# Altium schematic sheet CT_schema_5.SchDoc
size 373 x 245 mm
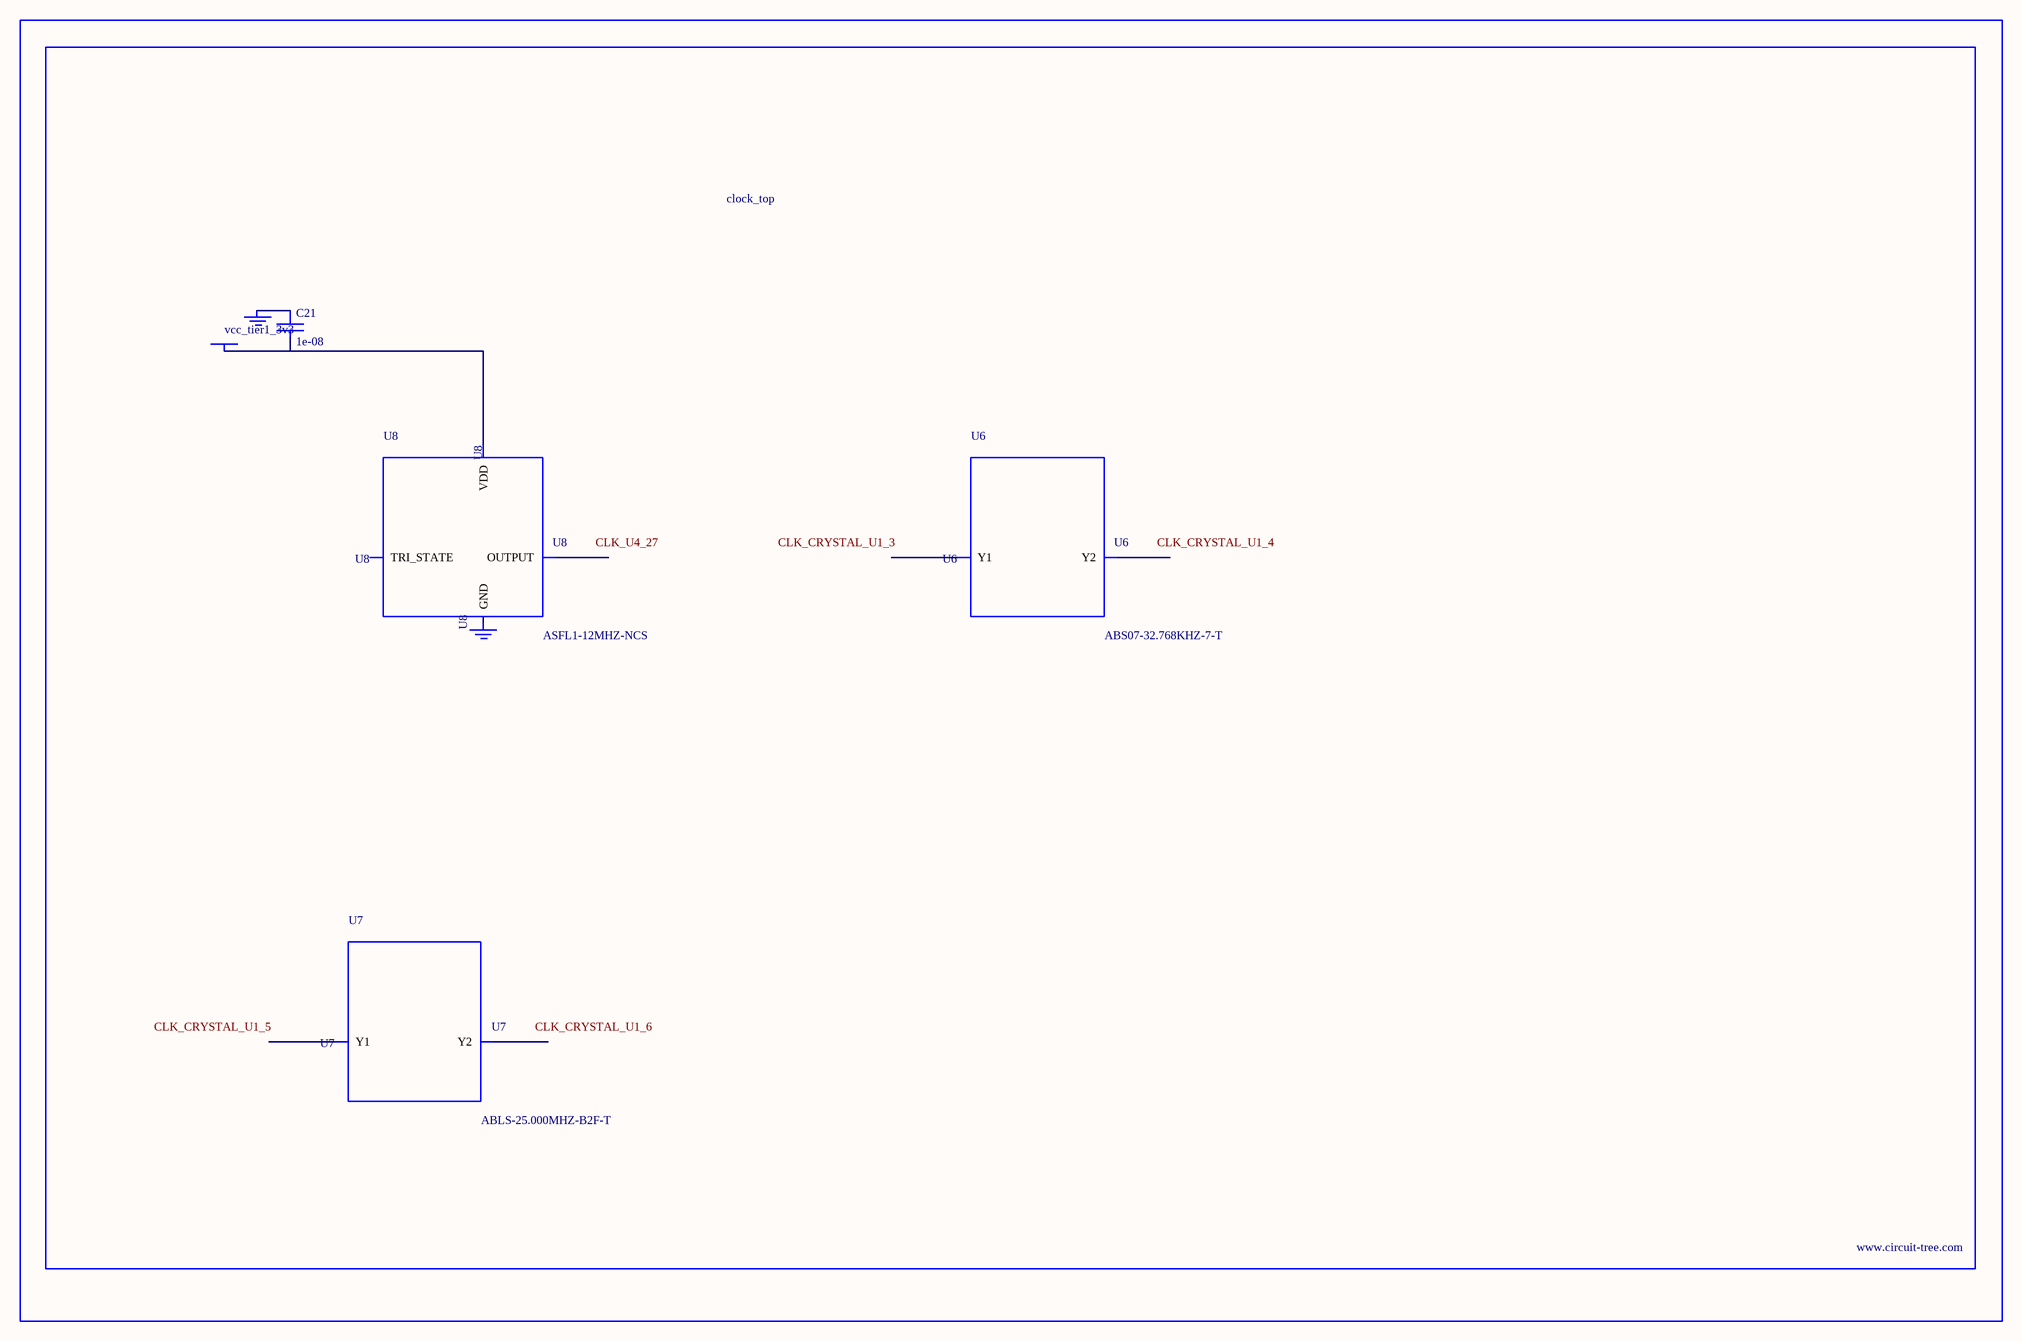
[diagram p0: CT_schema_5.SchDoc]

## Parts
BORDER4  (no value)
C21  1e-08  [C0402]
GND_INSTANCE_4_0  (no value)
GND_INSTANCE_4_1  (no value)
POWER_INSTANCE_4_0  vcc_tier1_3v3
U6  ABS07-32.768KHZ-7-T  [ABS07-32.768KHZ-7-T]
U7  ABLS-25.000MHZ-B2F-T  [ABLS-25.000MHZ-B2F-T]
U8  ASFL1-12MHZ-NCS  [ASFL1]

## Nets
NetC21_1: C21.1 GND_INSTANCE_4_0.0(GND)
NetC21_2: C21.2 POWER_INSTANCE_4_0.0(PWR) U8.4(VDD)

Not connected (* = marked no-connect by the designer): GND_INSTANCE_4_1 0(GND); U6 1(Y1) 2(Y2); U7 1(Y1) 2(Y2); U8 1(TRI_STATE) 2(GND) 3(OUTPUT)

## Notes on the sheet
- Labels drawn without touching a wire or pin: CLK_CRYSTAL_U1_3, CLK_CRYSTAL_U1_4, CLK_CRYSTAL_U1_5, CLK_CRYSTAL_U1_6, CLK_U4_27

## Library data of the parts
BORDER4 = BORDER_PAGE4
C21 = C0402C103K3RAC
GND_INSTANCE_4_0 GND_INSTANCE_4_1 = GND
POWER_INSTANCE_4_0 = PWR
